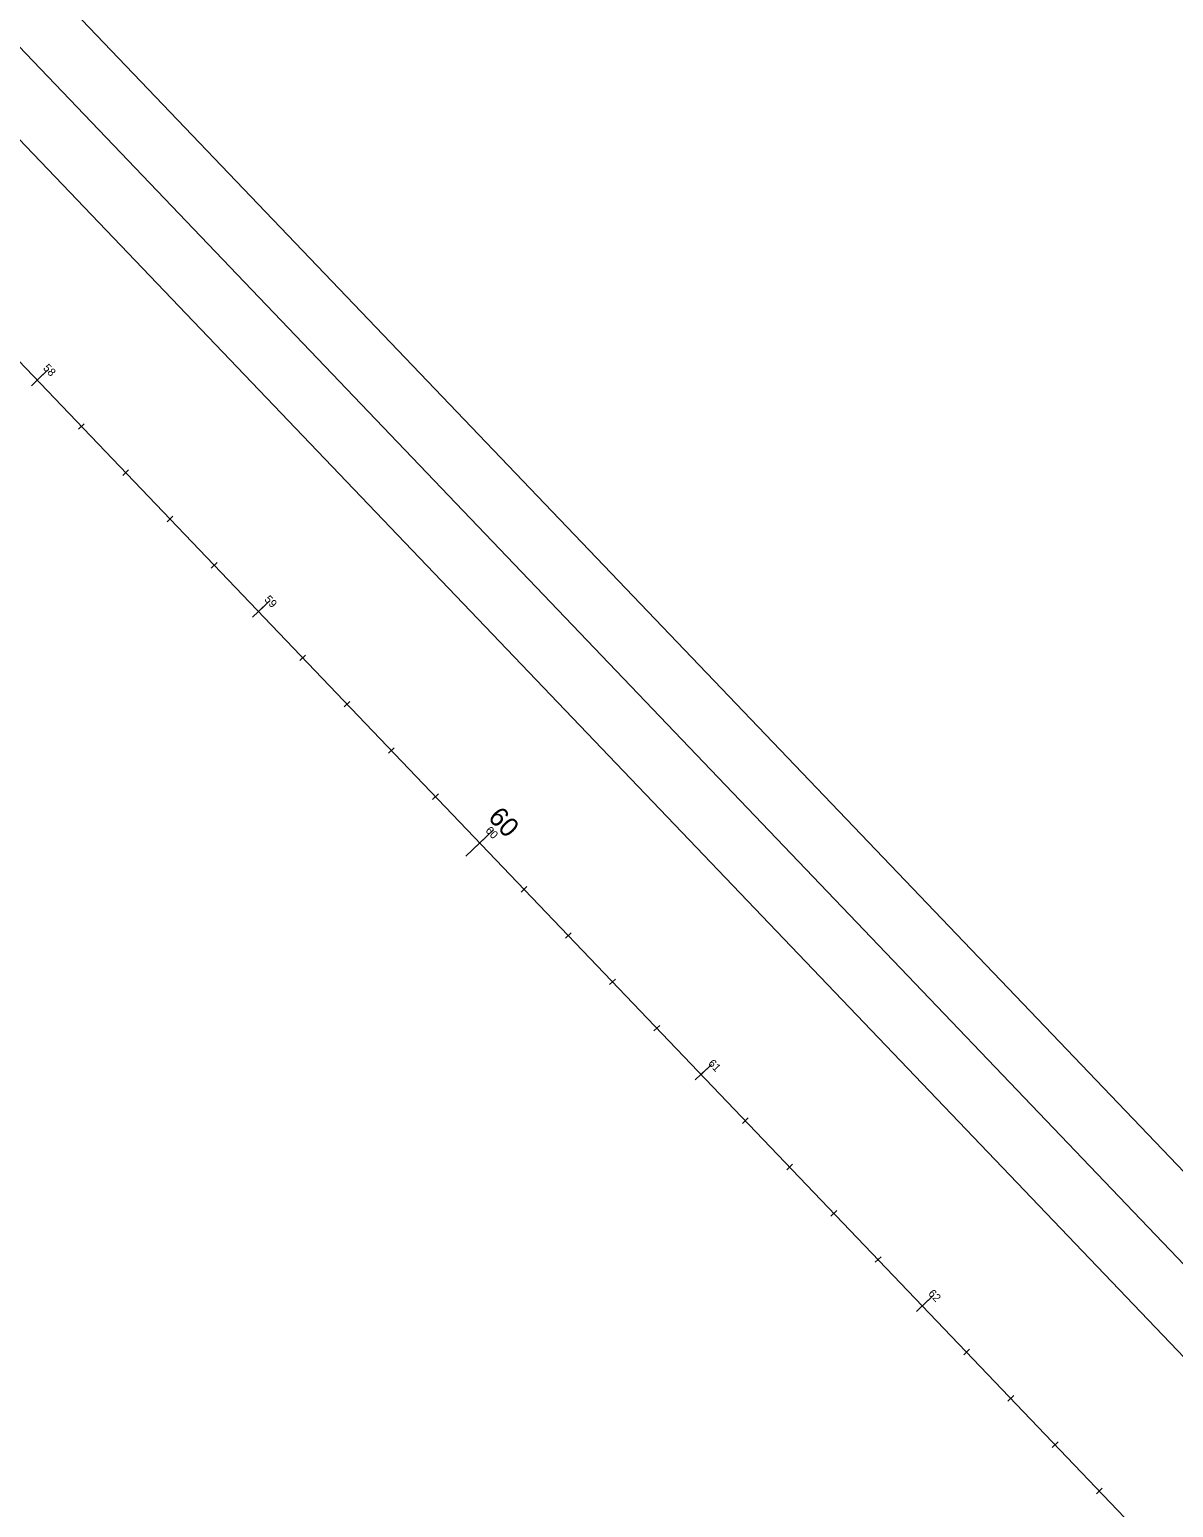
# Model space of a CAD drawing. Extents: x 1708585 to 1714116, y 541444 to 545437.
# Drawn here: x 1711437.5 to 1711794.7, y 544447.8 to 544909.5 of the extents above; entities that cross this region are included whole.
import ezdxf

# ---------------------------------------------------------------- set-up
doc = ezdxf.new("R2010")
doc.units = 0
for name, color, linetype in [('CL_Highway_2', 7, 'Continuous'), ('CL_Highway_2_40_Sta', 7, 'Continuous'), ('CL_Highway_2_Sta', 7, 'Continuous'), ('CL_Railroad', 7, 'Continuous')]:
    doc.layers.add(name, color=color, linetype=linetype)

msp = doc.modelspace()

# ---------------------------------------------------------------- linework, layer by layer
at = {"layer": 'CL_Highway_2'}
msp.add_line((1710887.1, 545378.25), (1711975.18, 544239.94), dxfattribs=at)
at = {"layer": 'CL_Highway_2_40_Sta'}
for points in [[(1711441.69, 544801.68), (1711438.08, 544798.22)], [(1711454.61, 544786.36), (1711452.8, 544784.63)], [(1711468.43, 544771.9), (1711466.62, 544770.17)], [(1711482.25, 544757.44), (1711480.44, 544755.71)], [(1711496.07, 544742.98), (1711494.26, 544741.26)], [(1711510.79, 544729.39), (1711507.17, 544725.94)], [(1711523.7, 544714.07), (1711521.9, 544712.34)], [(1711537.52, 544699.61), (1711535.72, 544697.88)], [(1711551.34, 544685.15), (1711549.54, 544683.43)], [(1711565.16, 544670.7), (1711563.36, 544668.97)], [(1711579.89, 544657.1), (1711576.27, 544653.65)], [(1711592.8, 544641.78), (1711590.99, 544640.05)], [(1711606.62, 544627.32), (1711604.81, 544625.6)], [(1711620.44, 544612.87), (1711618.63, 544611.14)], [(1711634.26, 544598.41), (1711632.45, 544596.68)], [(1711648.98, 544584.81), (1711645.37, 544581.36)], [(1711661.9, 544569.49), (1711660.09, 544567.77)], [(1711675.72, 544555.04), (1711673.91, 544553.31)], [(1711689.54, 544540.58), (1711687.73, 544538.85)], [(1711703.36, 544526.12), (1711701.55, 544524.39)], [(1711718.08, 544512.53), (1711714.47, 544509.07)], [(1711731, 544497.21), (1711729.19, 544495.48)], [(1711744.82, 544482.75), (1711743.01, 544481.02)], [(1711758.64, 544468.29), (1711756.83, 544466.56)], [(1711772.46, 544453.83), (1711770.65, 544452.11)]]:
    msp.add_lwpolyline(points, dxfattribs=at)
at = {"layer": 'CL_Highway_2_Sta'}
for points in [[(1711443.14, 544803.06), (1711439.88, 544799.95)], [(1711512.23, 544730.77), (1711508.98, 544727.66)], [(1711582.42, 544659.52), (1711573.74, 544651.23)], [(1711650.43, 544586.2), (1711647.18, 544583.09)], [(1711719.53, 544513.91), (1711716.27, 544510.8)]]:
    msp.add_lwpolyline(points, dxfattribs=at)
at = {"layer": 'CL_Railroad'}
for p, q in [((1710952.7, 545436.87), (1713371.13, 542906.81)), ((1710938.24, 545423.05), (1713356.67, 542892.99)), ((1710923.78, 545409.23), (1713342.21, 542879.17))]:
    msp.add_line(p, q, dxfattribs=at)

# ---------------------------------------------------------------- texts
at = {"layer": 'CL_Highway_2_40_Sta'}
for s, p in [('58', (1711441.58, 544803.6)), ('59', (1711510.67, 544731.32)), ('60', (1711579.69, 544659.12)), ('61', (1711649.23, 544586.36)), ('62', (1711717.94, 544514.48))]:
    msp.add_text(s, height=2.5, rotation=313.7074, dxfattribs=at).set_placement(p)
at = {"layer": 'CL_Highway_2_Sta'}
msp.add_text('60', height=6, rotation=313.7074, dxfattribs=at).set_placement((1711580.38, 544663.1))

doc.saveas('drawing.dxf')
